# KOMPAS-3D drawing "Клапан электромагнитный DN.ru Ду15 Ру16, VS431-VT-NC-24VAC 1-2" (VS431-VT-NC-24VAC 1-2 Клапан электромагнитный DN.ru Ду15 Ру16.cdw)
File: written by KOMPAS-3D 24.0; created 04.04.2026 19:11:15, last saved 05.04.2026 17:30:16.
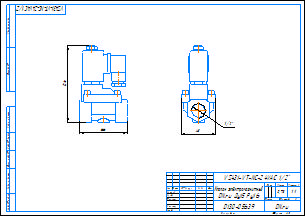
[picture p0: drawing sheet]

Document properties: c3d_UniqueCompID: ef56311e-7521-43dc-8291-0e6108b3d81d; Обозначение: VS400-ET-NC-220VAC 1-2; Наименование: Клапан электромагнитный DN.ru Ду15 Ру16; Автор: artio; Класс точности: c; Знак неуказанной шероховатости: Шероховатость не задана; Рассекать на разрезах: Да; c3d_UniqueCompID: ef56311e-7521-43dc-8291-0e6108b3d81d; Обозначение: VS400-ET-NC-220VAC 3-8; Наименование: Клапан электромагнитный DN.ru Ду10 Ру16; Автор: artio; Класс точности: c; Знак неуказанной шероховатости: Шероховатость не задана; Рассекать на разрезах: Да; Автор: artio; Форматы листов документа: A3; Полное имя файла: VS431-VT-NC-24VAC 1-2 Клапан электромагнитный DN.ru Ду15 Ру16.m3d; Масса: 0.732; Наименование: Клапан электромагнитный DN.ru Ду15 Ру16; Количество листов документа: 1; Примечание: D130-05639

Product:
- Body: Тело 1  | qty 1
    Масса: 1.030062
- Part/product: Клапан электромагнитный DN.ru Ду15 Ру16  | designation VS431-VT-NC-24VAC 1-2
    Масса: 0.732
    Раздел спецификации: Прочие изделия
    Примечание: D130-05639
    additional columns: ef56311e-7521-43dc-8291-0e6108b3d81d; VS400-ET-NC-220VAC 1-2; artio; c; Шероховатость не задана; Да

Views: Вид 1, Спереди, Проекционный вид 2
Referenced files in C:\Users\artio\OneDrive\Рабочий стол\Клапан электромагнитный DN.ru\VS400-ET-NC\VS400-ET-NC-24VDC\: VS400-ET-NC-24VDC 3-8 Клапан электромагнитный DN.ru Ду10 Ру16.m3d
Referenced files in C:\Users\artio\OneDrive\Рабочий стол\Клапан электромагнитный DN.ru\VS431\VS431-VT-NC\VS431-VT-NC-24VAC\Ду15\: VS431-VT-NC-24VAC 1-2 Клапан электромагнитный DN.ru Ду15 Ру16.m3d
Referenced files in C:\Users\artio\OneDrive\Рабочий стол\Клапан электромагнитный DN.ru\VS400-ET-NC\: VS400-ET-NC-24VDC 3-8 Клапан электромагнитный DN.ru Ду10 Ру16.cdw
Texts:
  VS431-VT-NC-24VAC 1-2
  Клапан электромагнитный
  DN.ru Ду15 Ру16
  VS431-VT-NC-24VAC 1/2"
  VS431-VT-NC-24VAC 1/2"-
  Клапан электромагнитный DN.ru Ду15 Ру16
  VS431-VT-NC-24VAC 1-2 Клапан электромагнитный DN.ru Ду15 Ру16
Dimensions and other numbers on the sheet: 0; 3; 2; 4; 48; 1/2"; 66; 106; 1:1; 1; 0,73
